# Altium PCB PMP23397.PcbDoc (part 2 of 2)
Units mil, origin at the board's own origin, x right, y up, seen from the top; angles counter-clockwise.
Board outline 1800 x 1800 mil, 2 copper layers (Top Layer, Bottom Layer), stack 62 mil thick; 47 components, 18 nets, 94 pads, 33 vias.
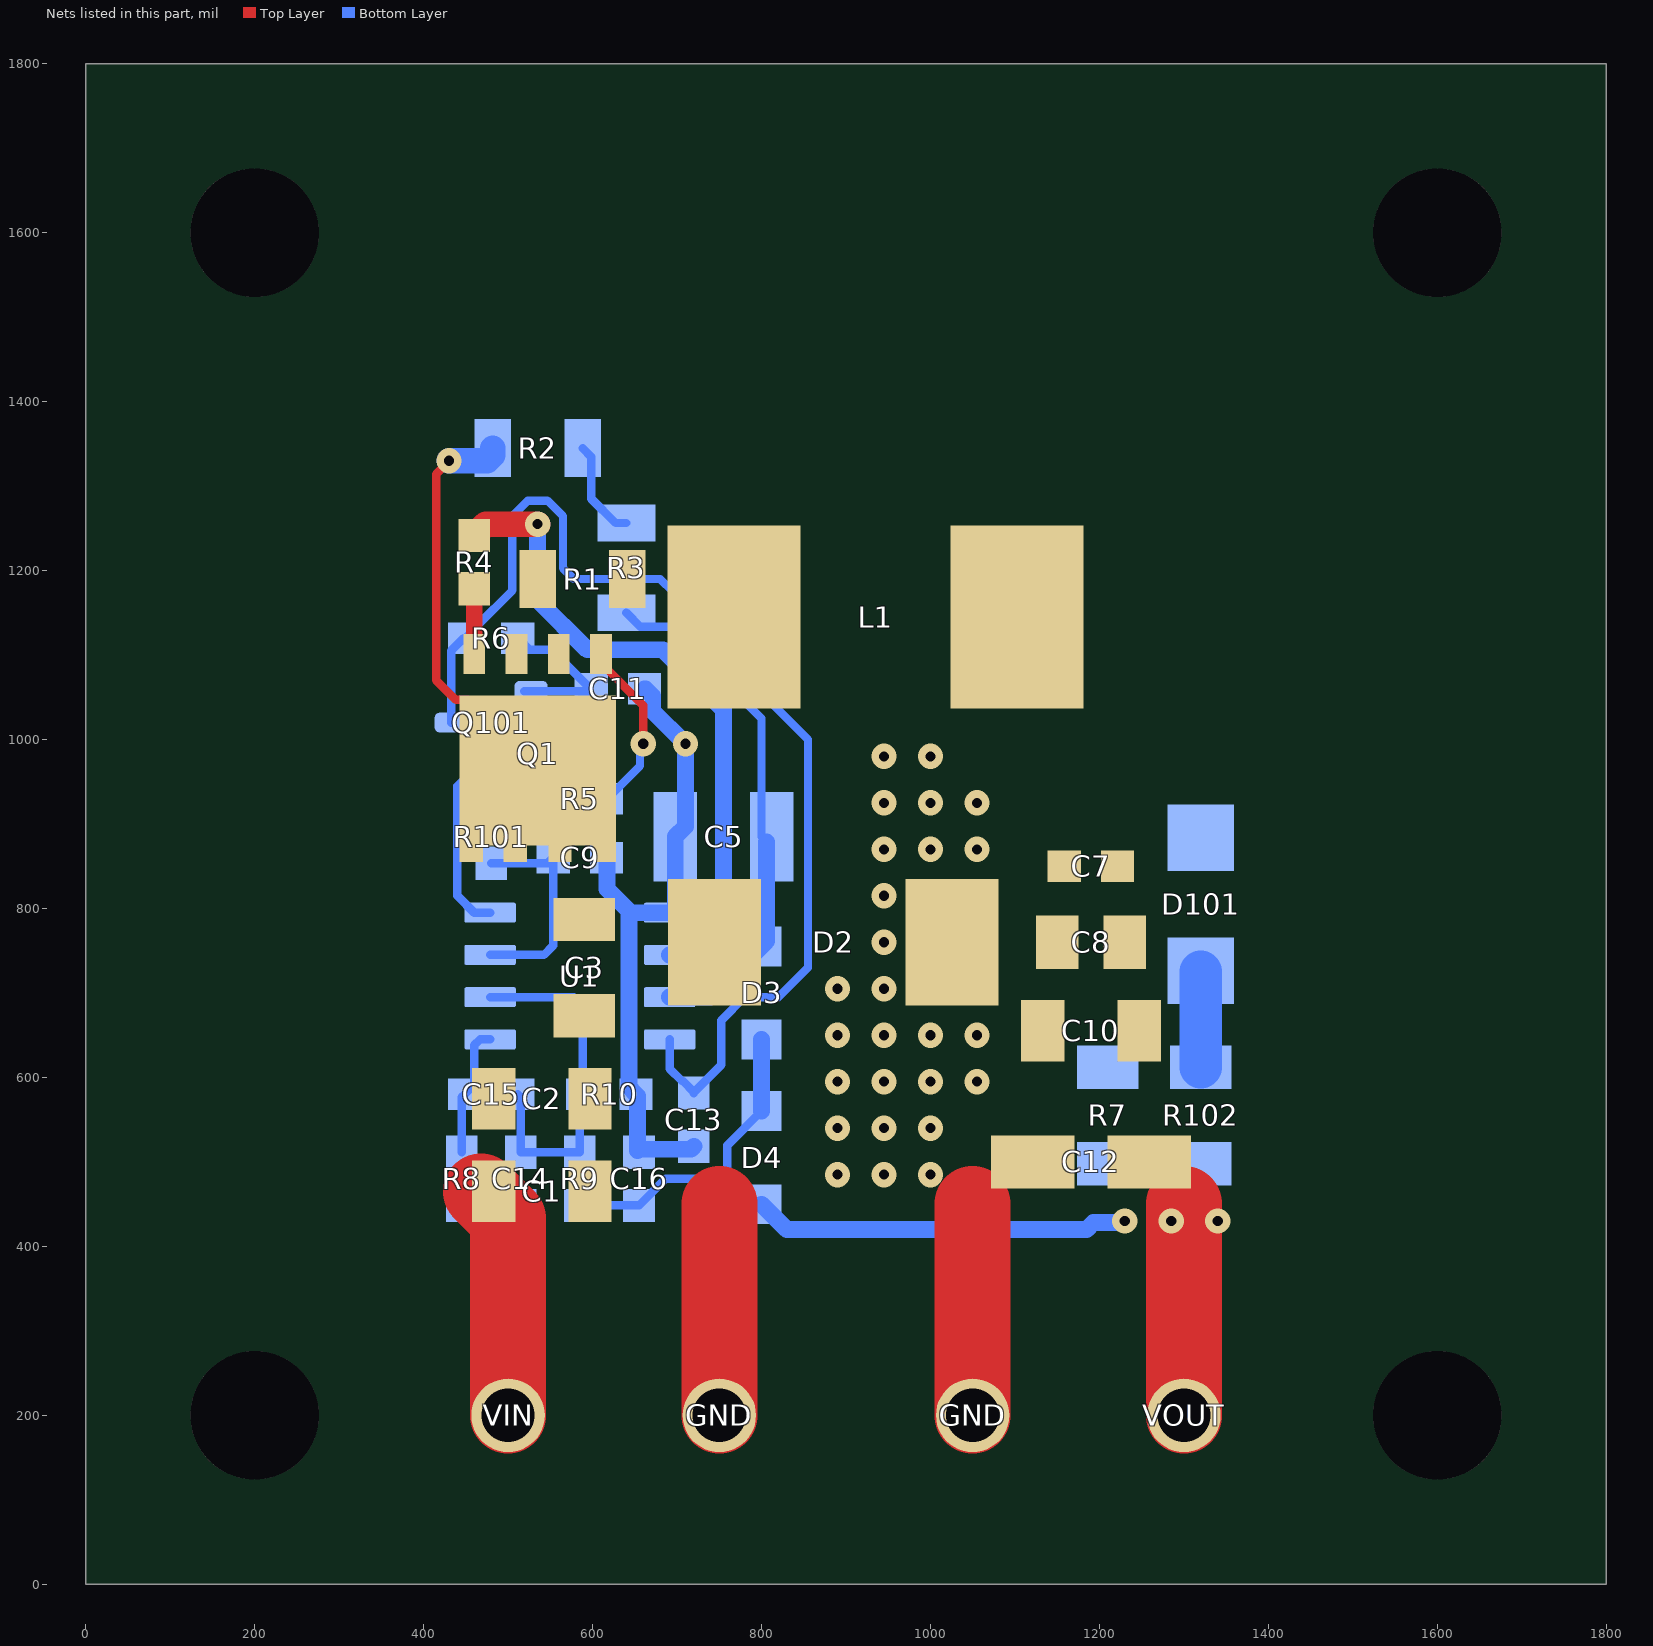
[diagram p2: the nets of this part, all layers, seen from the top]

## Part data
C1 C2 C3: library part CMP-0008793-2, "CAP, CERM, 0.22 uF, 250 V, +/- 10%, X7T, AEC-Q200 Grade 1, 1206", Cap_Case=1206, Manufacturer=TDK, Supplier Part Number 1=445-8798-1-ND, TempCo=X7T, Tolerance_%=10%, Value1=Unknown, Value2=250V, ValueDisplayed=0.22uF
C5: library part CMP-0009213-2, "CAP, CERM, 22 uF, 25 V, +/- 10%, X5R, 1210", Cap_Case=1210, Manufacturer=MuRata, Supplier Part Number 1=81-GRM32ER61E226KE15, TempCo=X5R, Tolerance_%=10%, Value1="0.002 ohm", Value2=25V, ValueDisplayed=22uF
C7 C13 C14 C16: library part CMP-0007415-4, "CAP, CERM, 0.22 uF, 25 V, +/- 10%, X7R, 0603", Cap_Case=0603, Manufacturer=MuRata, Supplier Part Number 1=490-3290-1-ND, TempCo=X7R, Tolerance_%=10%, Value1=Unknown, Value2=25V, ValueDisplayed=0.22uF
C8: library part CMP-0008342-2, "CAP, CERM, 2.2 uF, 25 V, +/- 10%, X7R, 0805", Cap_Case=0805, Manufacturer=MuRata, Supplier Part Number 1=490-3331-1-ND, TempCo=X7R, Tolerance_%=10%, Value1="0.005 ohm", Value2=25V, ValueDisplayed=2.2uF
C9: library part CMP-0007171-4, "CAP, CERM, 100 pF, 50 V, +/- 5%, C0G/NP0, 0603", Cap_Case=0603, Manufacturer=MuRata, Supplier Part Number 1=490-1427-1-ND, TempCo=C0G/NP0, Tolerance_%=5%, Value1=Unknown, Value2=50V, ValueDisplayed=100pF
C10: library part CMP-0082252-1, "CAP, CERM, 10 µF, 25 V,+/- 20%, X7R, AEC-Q200 Grade 1, 1206", Cap_Case=1206, Manufacturer=MuRata, Supplier Part Number 1=490-6519-1-ND, TempCo=X7R, Tolerance_%=20%, Value2=25V, ValueDisplayed=10µF
C11 C15: library part CMP-0007414-5, "CAP, CERM, 2200 pF, 25 V, +/- 10%, X7R, 0603", Cap_Case=0603, Manufacturer=MuRata, Supplier Part Number 1=GRM188R71E222KA01D-ND, TempCo=X7R, Tolerance_%=10%, Value1=Unknown, Value2=25V, ValueDisplayed=2200pF
C12: library part CMP-0010700-1, "CAP, AL, 22 uF, 16 V, +/- 20%, 1.35 ohm, AEC-Q200 Grade 2, SMD", Cap_Case=B, Manufacturer=Panasonic, Supplier Part Number 1=PCE3786CT-ND, Tolerance_%=20%, Value1="1.35 ohm", Value2=16V, ValueDisplayed=22uF
D2: library part CMP-0077028-2, "Diode, Ultrafast, 400 V, 3 A, SMC", Manufacturer=Vishay-Semiconductor, Value1=3A, Value2=1.1V
D3 D4: library part CMP-0029179-2, "Diode, Standard Recovery Rectifier, 200 V, 0.2 A, SOD-123F", Manufacturer=Nexperia, Value1=0.2A, Value2=1.25V
D101: library part CMP-0084951-1, "Diode, TVS, Uni, 14 V, 23.2 Vc, 400 W, 17.2 A, SMA", Manufacturer=Littelfuse, Value1=23.2V
GND GND: library part CMP-0055148-1, "Test Point, Multipurpose, Black, TH", Color=Black, Manufacturer=Keystone, Supplier Part Number 1=36-5011-ND
H1 H2 H3 H4: library part CMP-0003690-1, Manufacturer=Keystone, Supplier Part Number 1=36-4824-ND
L1: library part CMP-0061928-2, "Inductor, Shielded Drum Core, Ferrite, 680 uH, 0.75 A, 1.04 ohm, SMD", Manufacturer=Coilcraft, PartNumber=MSS1278-684KLB, Value1="1.04 ohm", Value2=0.75A, ValueDisplayed=680uH
LOGO1: library part CMP-0074837-1, "IEC 61010-1 Hot Surface Warning"
LOGO2: library part CMP-0074835-1, "IEC 61010-1 High Voltage Warning"
Logo3: library part CMP-0074769-1
Logo4: library part CMP-0074847-1, "FCC_disclaimer"
Logo5: library part CMP-0074836-1, "IEC 61010-1 Caution Warning"
Q1: library part CMP-0001102-3, "MOSFET, N-CH, 250 V, 10.9 A, PG-TDSON-8", Alternate Manufacturer=None, Manufacturer="Infineon Technologies", Supplier Part Number 1=BSC16DN25NS3GCT-ND, Value2="8.6 nC"
Q101: library part CMP-0000385-2, "Transistor, NPN, 40 V, 0.15 A, SOT-23", Manufacturer="Fairchild Semiconductor", Supplier Part Number 1=MMBT2222AFSCT-ND, Value1="0.15 A", Value2=300
R1: library part CMP-0016745-3, "RES, 1.00, 1%, 0.25 W, AEC-Q200 Grade 0, 1206", Manufacturer=Vishay-Dale, Power_W=250mW, Supplier Part Number 1=53K1855, TempCo="100 ppm/C", Tolerance_%=1%, Value2=0.25W, Value_Code=1R00, ValueDisplayed=1.00
R2 R3: library part CMP-0018626-3, "RES, 20 k, 5%, 0.25 W, AEC-Q200 Grade 0, 1206", Manufacturer=Vishay-Dale, Power_W=250mW, Supplier Part Number 1=541-20KECT-ND, TempCo="200 ppm/C", Tolerance_%=5%, Value2=0.25W, Value_Code=20k0, ValueDisplayed=20k
R4: library part CMP-0025821-4, "RES, 4.7, 5%, 0.1 W, AEC-Q200 Grade 0, 0603", Manufacturer=Vishay-Dale, Power_W=100mW, Supplier Part Number 1=541-4.7GCT-ND, TempCo="200 ppm/C", Tolerance_%=5%, Value2=0.1W, Value_Code=4R70, ValueDisplayed=4.7
R5: library part CMP-0022371-4, "RES, 3.01 k, 1%, 0.1 W, AEC-Q200 Grade 0, 0603", Manufacturer=Vishay-Dale, Power_W=100mW, Supplier Part Number 1=541-3.01KHCT-ND, TempCo="100 ppm/C", Tolerance_%=1%, Value2=0.1W, Value_Code=3k01, ValueDisplayed=3.01k
R6 R9 R101: library part CMP-0021998-4, "RES, 10.0 k, 1%, 0.1 W, AEC-Q200 Grade 0, 0603", Manufacturer=Vishay-Dale, Power_W=100mW, Supplier Part Number 1=541-10.0KHCT-ND, TempCo="100 ppm/C", Tolerance_%=1%, Value2=0.1W, Value_Code=10k0, ValueDisplayed=10.0k
R7: library part CMP-0018689-3, "RES, 4.7 k, 5%, 0.25 W, AEC-Q200 Grade 0, 1206", Manufacturer=Vishay-Dale, Power_W=250mW, Supplier Part Number 1=541-4.7KECT-ND, TempCo="200 ppm/C", Tolerance_%=5%, Value2=0.25W, Value_Code=4k70, ValueDisplayed=4.7k
R8 R10: library part CMP-0022277-4, "RES, 2.49 k, 1%, 0.1 W, AEC-Q200 Grade 0, 0603", Manufacturer=Vishay-Dale, Power_W=100mW, Supplier Part Number 1=541-2.49KHCT-ND, TempCo="100 ppm/C", Tolerance_%=1%, Value2=0.1W, Value_Code=2k49, ValueDisplayed=2.49k
R102: library part CMP-0018575-3, "RES, 100, 5%, 0.25 W, AEC-Q200 Grade 0, 1206", Manufacturer=Vishay-Dale, Power_W=250mW, Supplier Part Number 1=541-100ECT-ND, TempCo="200 ppm/C", Tolerance_%=5%, Value2=0.25W, Value_Code=100R, ValueDisplayed=100
U1: library part CMP-0033671-1, "Buck, Boost, Flyback, Forward Converter, SEPIC Regulator Positive Output Step-Up, Step-Down, Step-Up/Step-Down DC-DC Controller IC 8-SOIC", Digikey Part Number=296-UCC28C52DRCT-ND, Manufacturer="Texas Instruments", Max Supply Voltage=28V, Mouser Part Number=595-UCC28C52DR, Nominal Supply Current=1.3mA, Operating Temperature Range="-40°C to +125°C", Switching Frequency=1MHz
VIN VOUT: library part CMP-0055147-1, "Test Point, Multipurpose, Red, TH", Color=Red, Manufacturer=Keystone, Supplier Part Number 1=36-5010-ND

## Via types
v1: diameter 30, hole 12, Top Layer to Bottom Layer, tented top, 33 vias

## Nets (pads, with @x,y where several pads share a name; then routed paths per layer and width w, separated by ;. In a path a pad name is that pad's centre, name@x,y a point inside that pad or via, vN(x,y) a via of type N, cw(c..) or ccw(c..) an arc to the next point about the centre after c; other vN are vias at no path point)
GND: C1.2 C2.2 C3.2 C7.2 C8.2 C10.2 C12.2 D2.2 D101.2 GND.1 R7.1 | length 500
  Top Layer w90: GND.1@750,200 750,450 ; GND.1@1050,200 1050,450
  other v1: 890,485 945,485 1000,485 890,540 945,540 1000,540 890,595 945,595 1000,595 1055,595 890,650 945,650 1000,650 1055,650 890,705 945,705 945,760 945,815 945,870 1000,870 1055,870 945,925 1000,925 1055,925 945,980 1000,980
IC_GND: C5.2 C9.1 C11.2 C13.2 C16.1 D2.1 L1.1 R1.1 R10.1 U1.5 | length 775.5
  Bottom Layer w20: C9.1@616.5,860 616.98,859.51 616.98,823.01 642.91,797.09 642.91,795 ; C11.2@661.5,1060 662.48,1060 671.18,1051.3 671.18,1033.82 v1(710,995) 710,897.09 C5.2@697.91,885 697.91,796.81 696.1,795 U1.5@691.3,795 642.91,795 ; C13.2@720,518.5 716.5,515 655,515 653.25,513.25 653.25,578.25 R10.1@651.5,580 642.91,588.58 642.91,795
NetC1_1: C1.1 C2.1 C3.1 Q1.5 Q1.6 Q1.7 Q1.8 Q1.9 R2.1 VIN.1 | length 771.6
  Top Layer w10: v1(430,1330) 430,1329.14 415,1314.14 415,1070 437.99,1047.01 451.42,1047.01 Q1.9@535,963.43
  Top Layer w90: C1.1@467.91,465 500,432.91 VIN.1@500,200
  Bottom Layer w30: v1(430,1330) 475.2,1330 481.85,1336.65 R2.1@481.85,1345
NetC5_1: C5.1 D3.1 R3.2 U1.7 | length 620.3
  Bottom Layer w10: R3.2@640,1150 656.65,1133.35 691.65,1133.35 800,1025 800,885 C5.1@806.04,878.96
  Bottom Layer w20: U1.7@691.3,695 739.88,695 D3.1@800,755.12 806.04,761.16 C5.1@806.04,878.96
NetC7_1: C7.1 C8.1 C10.1 C12.1 D4.2 L1.2 R7.2 R102.2 VOUT.1 | length 696.5
  Top Layer w90: VOUT.1@1300,200 1300,450
  Bottom Layer w20: D4.2@800,449.88 829.88,420 1185,420 1193.09,428.09 1228.09,428.09 v1(1230,430)
  other v1: 1285,430 1340,430
NetC9_2: C9.2 R5.2 R101.2 U1.3 | length 329.4
  Bottom Layer w10: U1.3@478.7,745 542.32,745 553.5,756.18 C9.2@553.5,860 ; R101.2@480,853.5 547.01,853.5 C9.2@553.5,860 ; R5.2@553.5,930 C9.2@553.5,860
NetC11_1: C11.1 Q101.1 R6.1 U1.4 | length 566.4
  Bottom Layer w10: U1.4@478.7,795 460,795 440,815 440,945 505,1010 547.52,1010 C11.1@594.92,1057.4 ; R6.1@511.5,1120 525.2,1106.3 551.22,1106.3 594.92,1062.6 C11.1@594.92,1057.4 ; Q101.1@519.37,1057.4 Q101.1@527.24,1057.4 C11.1@594.92,1057.4
NetC13_1: C13.1 Q101.3 R6.2 U1.8 | length 1368.1
  Bottom Layer w10: Q101.3@432.76,1020 432.76,1105.24 447.52,1120 R6.2@448.5,1120 449.49,1120 463.19,1133.7 463.19,1134.69 505,1176.5 505,1264.42 523.45,1282.87 546.55,1282.87 565,1264.42 565,1202.76 577.76,1190 680,1190 695,1175 695,1160 855,1000 855,730 820,695 780,695 752.37,667.37 752.37,614.85 C13.1@720,582.48 ; U1.8@691.3,645 691.3,610.2 705.31,596.18 706.3,596.18 C13.1@720,582.48 ; C13.1@720,581.5 C13.1@720,582.48
NetC14_1: C14.1 C15.2 R9.1 R10.2 U1.2 | length 428.4
  Bottom Layer w10: U1.2@478.7,695 577.76,695 588.5,684.25 R10.2@588.5,580 585,576.5 R9.1@585,511.5 C14.1@515,511.5 515,576.5 C15.2@511.5,580
NetC14_2: C14.2 R8.2 | length 70
  Bottom Layer w10: R8.2@445,448.5 C14.2@515,448.5
NetC15_1: C15.1 R8.1 U1.1 | length 154.4
  Bottom Layer w10: R8.1@445,511.5 445,576.5 C15.1@448.5,580 460,591.5 460,638.19 466.81,645 U1.1@478.7,645
NetC16_2: C16.2 D3.2 D4.1 R9.2 | length 363.6
  Bottom Layer w10: R9.2@585,448.5 C16.2@655,448.5 686.5,480 750,480 759.5,489.5 759.5,519.62 D4.1@800,560.12
  Bottom Layer w20: D4.1@800,560.12 D3.2@800,644.88
NetD101_1: D101.1 R102.1 | length 112.9
  Bottom Layer w50: R102.1@1320,612.09 D101.1@1320,725
NetQ1_1: Q1.1 Q1.2 Q1.3 R1.2 R5.1 | length 210.5
  Top Layer w10: Q1.1@610,1101.22 610,1090.39 660,1040.39 v1(660,995)
  Bottom Layer w10: R5.1@616.5,930 617.48,930 656.17,968.69 656.17,991.17 v1(660,995)
NetQ1_4: Q1.4 R4.1 | length 77.3
  Top Layer w20: Q1.4@460,1101.22 R4.1@460,1178.5
NetQ101_2: Q101.2 R101.1 | length 90
  Bottom Layer w10: R101.1@480,916.5 493.7,930.2 493.7,956.44 512.56,975.3 519.86,982.6 Q101.2@527.24,982.6
NetR2_2: R2.2 R3.1 | length 117.7
  Bottom Layer w10: R2.2@588.15,1345 598.5,1334.65 598.5,1285 627.2,1256.3 R3.1@640,1256.3
NetR4_2: R4.2 U1.6 | length 784.1
  Top Layer w30: R4.2@460,1241.5 460,1242.48 463.7,1246.18 464.69,1246.18 473.5,1255 v1(535,1255)
  Bottom Layer w20: v1(535,1255) 535,1165 593.7,1106.3 683.7,1106.3 755,1035 755,770 730,745 U1.6@691.3,745
pads on no net: H1.0 H1.MH H2.0 H2.MH H3.0 H3.MH H4.0 H4.MH

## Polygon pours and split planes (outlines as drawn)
GND on Bottom Layer "BOTTOM_LAYER_GND_P007" (solid, remove dead copper, pour order 7): 1260,400 1260,790 1400,790 1400,1400 720,1400 720,1155 845,1030 845,400
GND on Top Layer "TOP_LAYER_GND_P011" (solid, remove dead copper, pour order 11): 555,400 555,695 630,695 660,665 820,665 820,825 870,875 870,1015 1055,1015 1185,885 1185,400
IC_GND on Top Layer "TOP_LAYER_IC_GND_P010" (solid, remove dead copper, pour order 10): 850,1250 665,1250 635,1220 620,1220 620,1160 635,1160 690,1105 690,685 800,685 800,835 850,885
NetC1_1 on Top Layer "TOP_LAYER_NETC1_1_P009" (solid, remove dead copper, pour order 9): 400,400 400,1035 425,1060 490,995 653.11,995 653.11,743.11 630,720 535,720 530,715 530,630 545,615 545,400
no net on Top Layer "TOP_LAYER_NONET_P008" (solid, remove dead copper, pour order 8): 500,1075 500,1220 590,1220 595,1215 595,1140 600,1135 625,1135 625,1075
NetQ1_1 on Top Layer "TOP_LAYER_NETQ1_1_P006" (solid, remove dead copper, pour order 6): 500,1075 500,1220 590,1220 595,1215 595,1140 600,1135 625,1135 625,1075
NetC7_1 on Top Layer "TOP_LAYER_NETC7_1_P002" (solid, remove dead copper, pour order 2): 1400,1400 1025.49,1400 1025.49,1064.51 1200,890 1200,400 1400,400

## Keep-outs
Keep-Out Layer:
  text ".Layer_Name" at 577,-858.49 h60

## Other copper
Top Layer:
  text ".Layer_Name" at 577,-858.49 h60
Bottom Layer:
  region net NetC7_1: 1400,400 1400,535 1160,535 1160,400
  text ".Layer_Name" at 577,-858.49 h60

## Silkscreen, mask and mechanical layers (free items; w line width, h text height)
Top Overlay:
  lines w10: 400,400 1400,400 1400,1400 400,1400 400,400
  text "'.PRJ_Number'.PCB_Rev" at 550,1600 h120
  text ".Layer_Name" at 577,-858.49 h60
Bottom Overlay:
  lines w10: 400,400 1400,400 1400,1400 400,1400 400,400
  text ".Layer_Name" at 577,-858.49 h60
Top Paste:
  text ".Layer_Name" at 577,-858.49 h60
Bottom Paste:
  text ".Layer_Name" at 577,-858.49 h60
Top Solder:
  text ".Layer_Name" at 577,-858.49 h60
  text ".Layer_Name" at 577,-858.49 h60
Bottom Solder:
  text ".Layer_Name" at 577,-858.49 h60
Drill Guide:
  text ".Layer_Name" at 577,-858.49 h60
M1 Board Outline:
  the board outline again, w10
  text ".Layer_Name" at 577,-858.49 h60
M2 Board Dimensions:
  rectangle: 0,-275 125,-150
  rectangle: 125,-400 500,-275
  lines w7: 0,-275 1000,-275 ; 125,-400 125,-150 ; 250,-400 250,-150 ; 500,-400 500,-150 ; 750,-400 750,-150 ; 0,-400 1000,-400 1000,-150 0,-150 0,-400
  text ".Layer_Name" at 577,-858.49 h60
M3 3D STEP Top:
  text ".Layer_Name" at 577,-858.49 h60
M4 3D STEP Bottom:
  text ".Layer_Name" at 577,-858.49 h60
M5 Assembly Top:
  lines w10: -292,-930.17 6308,-930.17 ; -292,-726.83 6310,-726.83 ; -292,-523.5 -292,-1133.5 3713,-1133.5 6310,-1133.5 6310,-523.5 -291.5,-523.5 -291.5,-1133.5 1284,-1133.5 ; 2173,-1133.5 2173,-523.5 ; 3440,-726.83 3440,-523.5 ; 4280,-726.83 4280,-523.5 ; 4902,-1140 4902,-937.17
  text "COMPONENTS MARKED 'DNP' SHOULD NOT BE POPULATED." at 1153.5,-318.5 h60
  text "ASSEMBLY VARIANT:" at 1153,-434 h60
  text ".VariantName" at 2189,-434 h60
  text "PCB VIEWED FROM TOP SIDE" at -228.5,-655.67 h60
  text "BOARD #:" at 2248,-655.67 h60
  text ".PRJ_Number" at 2793.5,-655.67 h60
  text "REV:" at 3638,-655.67 h60
  text ".PCB_Rev" at 3929.5,-655.67 h60
  text "SVN REV:" at 4476,-655.67 h60
  text ".VersionControl_RevNumber" at 4982,-655.67 h60
  text "TID #:" at 2248,-859 h60
  text ".TID" at 2793.5,-859 h60
  text "PLOT NAME =" at -228.5,-1064.34 h60
  text ".plot_File_Name" at 577,-1064.34 h60
  text "GENERATED    :" at 2250,-1064.34 h60
  text ".Print_Date" at 3119.5,-1064.34 h60
  text ".Print_Time" at 3848.5,-1064.34 h60
  text "TEXAS INSTRUMENTS" at 5113,-1064.34 h60
M6 Assembly Bottom:
  lines w10: -292.5,-727.33 6309.5,-727.33 ; -290.5,-930.67 6309.5,-930.67 ; 1115.5,-1140.5 1115.5,-937.67 ; 1737.5,-727.33 1737.5,-524 ; 2577.5,-727.33 2577.5,-524 ; 3844.5,-1134 3844.5,-524 ; 4733.5,-1134 6309,-1134 6309,-524 -292.5,-524 -292.5,-1134 2304.5,-1134 6309.5,-1134 6309.5,-524
  text "COMPONENTS MARKED 'DNP' SHOULD NOT BE POPULATED." at 6102,-318 h60
  text ".VariantName" at 5058,-434 h60
  text "ASSEMBLY VARIANT:" at 6097,-434 h60
  text ".VersionControl_RevNumber" at 1035.5,-656.17 h60
  text "SVN REV:" at 1541.5,-656.17 h60
  text ".PCB_Rev" at 2088,-656.17 h60
  text "REV:" at 2379.5,-656.17 h60
  text ".PRJ_Number" at 3224,-656.17 h60
  text "BOARD #:" at 3769.5,-656.17 h60
  text "PCB VIEWED FROM BOTTOM SIDE" at 6246,-656.17 h60
  text ".TID" at 3224,-859.5 h60
  text "TID #:" at 3769.5,-859.5 h60
  text "TEXAS INSTRUMENTS" at 904.5,-1064.84 h60
  text ".Print_Time" at 2169,-1064.84 h60
  text ".Print_Date" at 2898,-1064.84 h60
  text "GENERATED    :" at 3767.5,-1064.84 h60
  text ".plot_File_Name" at 5440.5,-1064.84 h60
  text "PLOT NAME =" at 6246,-1064.84 h60
M9 Title Sheet:
  drawing of 57 lines, arcs and shapes, not listed
  text "1" at 739.84,8036.5 h70
  text "2" at 3235.5,8036.5 h70
  text "3" at 5724.84,8036.5 h70
  text "4" at 8231.51,8036.5 h70
  text "5" at 10730.5,8036.5 h70
  text "6" at 13235.5,8036.5 h70
  text "A" at -416.5,6893.5 h70
  text "A" at 14383.5,6893.5 h70
  text "B" at -416.5,4513.5 h70
  text "B" at 14383.5,4513.5 h70
  text "C" at -416.5,2138.5 h70
  text "C" at 14383.5,2138.5 h70
  text "PROJECT TITLE:" at 11343.5,277.5 h45
  text ".PRJ_Title" at 11393.5,144.17 h70
  text "DESIGNED FOR:" at 11343.5,-23.5 h45
  text ".PRJ_Customer" at 11393.5,-163.5 h70
  text "D" at -416.5,-231.5 h70
  text "D" at 14383.5,-231.5 h70
  text "FILE NAME:" at 11343.5,-323.5 h45
  text ".PCB_File_Name_No_Path" at 11393.5,-443.5 h70
  text "Texas Instruments (TI) and/or its licensors do not warrant the accuracy or completeness of this specification" at 6374,-605.34 h45
  text "ENGINEER:" at 11343.5,-613.5 h45
  text "LAYOUT BY:" at 12848.5,-613.5 h45
  text "or any information contained therein. TI and/or its licensors do not warrant that this design will meet" at 6329.01,-718 h45
  text ".PRJ_Engineer" at 11393.5,-768.49 h70
  text ".PCB_Layout" at 12899,-768.49 h70
  text "the specifications, will be suitable for your application or fit for any particular purpose, or will operate in" at 6329.01,-830.67 h45
  text ".Layer_Name" at 577,-858.49 h60
  text "ALTIUM DESIGNER VERSION:" at 12848.5,-923.5 h45
  text "an implementation. TI and/or its licensors do not warrant that the design is production worthy. You should" at 6329.01,-943.33 h45
  text "completely validate and test your design implementation to confirm the system functionality for your application." at 6374,-1056 h45
  text ".print_Scale" at 11393.5,-1056.83 h70
  text ".Application_BuildNumber" at 12899,-1056.83 h70
  text "1" at 739.84,-1263.5 h70
  text "2" at 3235.5,-1263.5 h70
  text "3" at 5724.84,-1263.5 h70
  text "4" at 8231.51,-1263.5 h70
  text "5" at 10730.5,-1263.5 h70
  text "6" at 13235.5,-1263.5 h70
M10 Fab Notes:
  drawing of 189 lines, arcs and shapes, not listed
  text "DESIGN INFORMATION" at 12382.02,6356.17 h60
  text "MIN. TRACK WIDTH:" at 11737.46,6224.05 h60
  text "8" at 12833.7,6224.05 h60
  text "MIL" at 12988.46,6224.05 h60
  text "7.874" at 12667.32,6102.36 h60
  text "MIN. CLEARANCE:" at 11737.46,6099.92 h60
  text "MIL" at 12988.46,6099.92 h60
  text "MIN. VIA PAD SIZE:" at 11737.46,5975.8 h60
  text "24" at 12803.71,5975.8 h60
  text "MIL" at 12988.46,5975.8 h60
  text "0.05mm (2MIL)" at 12432.46,5845.9 h60
  text "MINIMUM ANNULAR RING" at 11408.23,5837.67 h60
  text "EXTERNAL" at 13140.46,5837.67 h60
  text "PER" at 11608.23,5727.55 h60
  text "IPC-D-275 CLASS 2 LEVEL C" at 11828.23,5727.54 h60
  text "MIL, HOLES" at 13316.46,5627.07 h60
  text "+/-" at 12924,5618.48 h60
  text "+/-" at 13778,5618.48 h60
  text "REGISTRATION TOLERANCES:" at 11408.23,5617.42 h60
  text "METAL" at 12608,5617.42 h60
  text "5" at 13184.2,5617.42 h60
  text "3" at 14017.2,5617.42 h60
  text "MIL" at 14133.46,5617.42 h60
  text "HOLE SIZE TOLERANCE (UNLESS OTHERWISE SPECIFIED):" at 11408.23,5519.1 h60
  text "+/-" at 13778,5516.23 h60
  text "3" at 14017.2,5515.17 h60
  text "MIL" at 14133.46,5515.17 h60
  text "MATERIAL:" at 11333.46,5377.52 h60
  text "FR-4 High Tg" at 12319.9,5249 h60
  text "X" at 12175.46,5241.01 h60
  text "FR-4" at 11754.46,5236.49 h60
  text "OTHER" at 13242.46,5236.49 h60
  text "62 MIL (1.6mm) +/-10%" at 12074.56,5093.46 h60
  text "X" at 11954.46,5091.01 h60
  text "THICKNESS:" at 11408.23,5085.24 h60
  text "OTHER" at 13359.46,5085.24 h60
  text "TOLERANCE:" at 11408.23,4946.92 h60
  text "X" at 12256.46,4946.92 h60
  text "ANSI IPC-6012 TYPE 3 CLASS 2" at 12434.48,4946.92 h60
  text "OTHER +/-" at 12434.46,4802.73 h60
  text "BOW & TWIST:" at 11408.23,4657.54 h60
  text "X" at 12256.46,4657.54 h60
  text "ANSI IPC-6012 TYPE 3 CLASS 2" at 12434.48,4657.54 h60
  text "OTHER +/-" at 12434.46,4510.85 h60
  text "DRILLING:" at 11333.46,4380.23 h60
  text "NC_DRILL FILES" at 13094.46,4275.04 h60
  text "REFERENCE:" at 11408.23,4271.1 h60
  text "X" at 12065.46,4271.01 h60
  text "AS SHOWN" at 12243.46,4271.1 h60
  text "X" at 12966.46,4271.1 h60
  text "OTHER" at 13392.46,4128.85 h60
  text "PTH COPPER THICKNESS:" at 11407.91,4125.32 h60
  text "X" at 12547.14,4125.32 h60
  text "20-30 um" at 12675.14,4125.32 h60
  text "BOARD FINISH:" at 11333.46,3977.73 h60
  text "SILKSCREEN:" at 11488.68,3867.6 h60
  text "X" at 12446.46,3867.6 h60
  text "TOP" at 12563.46,3867.6 h60
  text "X" at 12956.46,3867.6 h60
  text "BOTTOM" at 13074.46,3867.6 h60
  text "SILKSCREEN COLOR:" at 11488.68,3712.41 h60
  text "X" at 12445.46,3712.41 h60
  text "WHITE" at 12563.46,3712.41 h60
  text "OTHER" at 13074.46,3712.41 h60
  text "X" at 12576.46,3568.96 h60
  text "GREEN" at 12694.46,3568.96 h60
  text "OTHER" at 13312.46,3568.96 h60
  text "SOLDER RESIST COLOR:" at 11488.68,3562.1 h60
  text "X" at 12576.46,3414.71 h60
  text "MATTE" at 12694.46,3414.71 h60
  text "SEMI-GLOSS" at 13312,3414.07 h60
  text "IMMERSION GOLD (ENIG)" at 12394.46,3241.94 h60
  text "ENEPIG" at 13732,3234.72 h60
  text "SURFACE FINISH:" at 11333.46,3233.72 h60
  text "X" at 12216.46,3233.72 h60
  text "IMM. TIN/SILVER OR EQUIV" at 11663,3096.4 h60
  text "OTHER" at 13094.46,3092.47 h60
  text "ARRAY/PANEL:" at 11333.46,2937.09 h60
  text "CUT AND TRIM PER M1 BOARD OUTLINE" at 12394.46,2928.87 h60
  text "N.C. ROUTE" at 12394.46,2792.9 h60
  text "X" at 13082.46,2792.9 h60
  text "V. SCORE" at 13260.46,2792.9 h60
  text "CERTIFICATION:" at 11333.46,2663.77 h60
  text "MATERIALS AND WORKMANSHIP FOR ALL PCBS" at 12058.46,2663.77 h60
  text "TO MEET OR EXCEED THE REQUIREMENTS OF:" at 12058.46,2569.71 h60
  text "X" at 11695.97,2441.08 h60
  text "ANSI IPC-A-600F CLASS ->" at 11823.96,2441.08 h60
  text "X" at 13471.97,2441.08 h60
  text "2" at 13581.96,2441.08 h60
  text "1" at 13266.96,2439.58 h60
  text "3" at 13935.96,2439.58 h60
  text "X" at 12507.97,2293.39 h60
  text "RoHS" at 12635.96,2293.39 h60
  text "OTHER" at 13280.36,2293.39 h60
  text "PER ORDER" at 13677.42,2293.39 h60
  text "ALL BOARDS MUST MEET OR EXCEED UL94-V0 REQUIREMENTS." at 11361,2139.57 h60
  text "PCB MUST BEAR THE UL94V-0 UL REGISTERED MATERIAL ID NUMBER" at 11361,2023.5 h60
  text "ADDITIONAL REQUIREMENTS:" at 11333.46,1854.08 h60
  text "MICROSECTION:" at 11408.23,1746.95 h60
  text "YES" at 12313.96,1746.95 h60
  text "REQUIRED" at 13175.46,1602.62 h60
  text "BARE BOARD ELEC. TEST:" at 11408.23,1599.76 h60
  text "NONE" at 12713.96,1599.76 h60
  text "X" at 13057.46,1599.76 h60
  text "PER ORDER" at 13767.46,1599.76 h60
  text "XX MIL VIAS REQUIRE NON-CONDUCTIVE FILL AND PLANARIZE" at 11576.38,1394.82 h59
  text "XX MIL VIAS REQUIRE CONDUCTIVE FILL AND PLANARIZE" at 11584.38,1290.84 h60
  text "OUTER XX MIL TRACES REQUIRE 50 OHM SINGLE-ENDED IMPEDANCE" at 11583.39,1127.46 h58
  text "LAYER 2 & 3 (INNER LAYERS) XX MIL WIDE, XX MIL SPACE / TRACES REQUIRE 100 OHM DIFFERENTIAL IMPEDANCE" at 11575.39,891.74 h60
  text ".Layer_Name" at 577,-858.49 h60
M11 Gerber Information:
  lines w10: -292,-930.17 6308,-930.17 ; -292,-726.83 6310,-726.83 ; -292,-523.5 -292,-1133.5 3713,-1133.5 6310,-1133.5 6310,-523.5 -291.5,-523.5 -291.5,-1133.5 1284,-1133.5 ; 2173,-1133.5 2173,-523.5 ; 3440,-726.83 3440,-523.5 ; 4280,-726.83 4280,-523.5 ; 4902,-1140 4902,-937.17
  text "ALL ARTWORK VIEWED FROM TOP SIDE" at -228.5,-655.67 h60
  text "BOARD #:" at 2248,-655.67 h60
  text ".PRJ_Number" at 2793.5,-655.67 h60
  text "REV:" at 3638,-655.67 h60
  text ".PCB_Rev" at 3929.5,-655.67 h60
  text "SVN REV:" at 4476,-655.67 h60
  text ".VersionControl_RevNumber" at 4982,-655.67 h60
  text "LAYER NAME =" at -228.5,-858.49 h60
  text "TID #:" at 2248,-859 h60
  text ".TID" at 2793.5,-859 h60
  text "PLOT NAME =" at -228.5,-1064.34 h60
  text ".plot_File_Name" at 577,-1064.34 h60
  text "GENERATED    :" at 2250,-1064.34 h60
  text ".Print_Date" at 3119.5,-1064.34 h60
  text ".Print_Time" at 3848.5,-1064.34 h60
  text "TEXAS INSTRUMENTS" at 5113,-1064.34 h60
M12 Stackup:
  drawing of 191 lines, arcs and shapes, not listed
  text "Layer" at 9821.59,7874.94 h60
  text "Name" at 10231.51,7874.94 h60
  text "Material" at 11161.25,7874.94 h60
  text "Thickness" at 12021.02,7874.94 h60
  text "Constant" at 12670.85,7874.94 h60
  text "Board Layer Stack" at 13240.71,7874.94 h60
  text "Top Overlay" at 10231.51,7754.94 h60
  text "Top Solder" at 10231.51,7634.94 h60
  text "Solder Resist" at 11161.25,7634.94 h60
  text "0.40mil" at 12021.02,7634.94 h60
  text "3.5" at 12670.85,7634.94 h60
  text "1" at 9821.59,7514.94 h60
  text "Top Layer" at 10231.51,7514.94 h60
  text "1.40mil" at 12021.02,7514.94 h60
  text "Dielectric1" at 10231.51,7394.94 h60
  text "FR-4 High Tg" at 11161.25,7394.94 h60
  text "59.20mil" at 12021.02,7394.94 h60
  text "4.8" at 12670.85,7394.94 h60
  text "2" at 9821.59,7274.94 h60
  text "Bottom Layer" at 10231.51,7274.94 h60
  text "1.40mil" at 12021.02,7274.94 h60
  text "Bottom Solder" at 10231.51,7154.94 h60
  text "Solder Resist" at 11161.25,7154.94 h60
  text "0.40mil" at 12021.02,7154.94 h60
  text "3.5" at 12670.85,7154.94 h60
  text "Bottom Overlay" at 10231.51,7034.94 h60
  text ".Layer_Name" at 577,-858.49 h60
M13 Component Bodies Top:
  text ".Layer_Name" at 577,-858.49 h60
M14 Component Bodies Bottom:
  text ".Layer_Name" at 577,-858.49 h60
M15 Courtyards Top:
  text ".Layer_Name" at 577,-858.49 h60
M16 Courtyards Bottom:
  text ".Layer_Name" at 577,-858.49 h60
Drill Drawing:
  circle w10: c5363.54,3290.72 r27.56
  lines w10: 5335.98,3015.1 5391.1,3015.1 5391.1,3070.22 5335.98,3070.22 5335.98,3015.1 ; 5335.98,3194.25 5391.1,3194.25 5363.54,3139.13 5335.98,3194.25
  lines w12: 5286,2977.89 8512.8,2977.89 ; 5286,3349.97 8512.8,3349.97 ; 5623.36,2853.87 5623.36,3474 ; 5955.06,2853.87 5955.06,3474 ; 6590.91,2853.87 6590.91,3474 ; 6849.71,2853.87 6849.71,3474 ; 7224.46,2853.87 7224.46,3474 ; 7947,2853.87 7947,3474 ; 5286,2853.87 8512.8,2853.87 8512.8,3474 5286,3474 5286,2853.87
  text "Symbol" at 5360.42,3387.18 h72
  text "Quantity" at 5660.57,3387.18 h72
  text "Finished Hole Size" at 5992.26,3387.18 h72
  text "Plated" at 6628.12,3387.18 h72
  text "Hole Type" at 6886.92,3387.18 h72
  text "Drill Layer Pair" at 7261.67,3387.18 h72
  text "Hole Tolerance" at 7984.21,3387.18 h72
  text "4" at 5660.57,3263.15 h60
  text "152.00mil (3.861mm)" at 5992.26,3263.15 h60
  text "NPTH" at 6628.12,3263.15 h60
  text "Round" at 6886.92,3263.15 h60
  text "Top Layer - Bottom Layer" at 7261.67,3263.15 h60
  text "33" at 5660.57,3139.13 h60
  text "12.00mil (0.305mm)" at 5992.26,3139.13 h60
  text "PTH" at 6628.12,3139.13 h60
  text "Round" at 6886.92,3139.13 h60
  text "Top Layer - Bottom Layer" at 7261.67,3139.13 h60
  text "4" at 5660.57,3015.1 h60
  text "63.00mil (1.600mm)" at 5992.26,3015.1 h60
  text "PTH" at 6628.12,3015.1 h60
  text "Round" at 6886.92,3015.1 h60
  text "Top Layer - Bottom Layer" at 7261.67,3015.1 h60
  text "41 Total" at 5660.57,2891.07 h60
  text ".Layer_Name" at 577,-858.49 h60
M17 Embedded Cavity:
  text ".Layer_Name" at 577,-858.49 h60
M18 Embedded Assembly:
  text ".Layer_Name" at 577,-858.49 h60
M19 Embedded Keepout:
  text ".Layer_Name" at 577,-858.49 h60

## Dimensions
0,-400 to 1000,-400 on M2 Board Dimensions
0,1800 to 1800,0 on M2 Board Dimensions
1800,1800 to 0,1800 on M2 Board Dimensions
